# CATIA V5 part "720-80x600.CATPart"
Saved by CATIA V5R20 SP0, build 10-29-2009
Part number: 720-80x600
Definition: NONE
Nomenclature: 720-80x600
Source: Unknown
Description: 720-80x600
Bounding box of the stored display mesh (mm): x 0 to 600, y -40 to 40, z -40 to 40
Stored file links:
  C:\Users\Utente\Desktop\IO LAVORO\3D X SITO CF\X SITO\720\720-80x600.CATPart

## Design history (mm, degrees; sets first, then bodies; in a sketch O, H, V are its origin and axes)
Body1 "720-80x600" (main body)
  Solid1: solid without history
